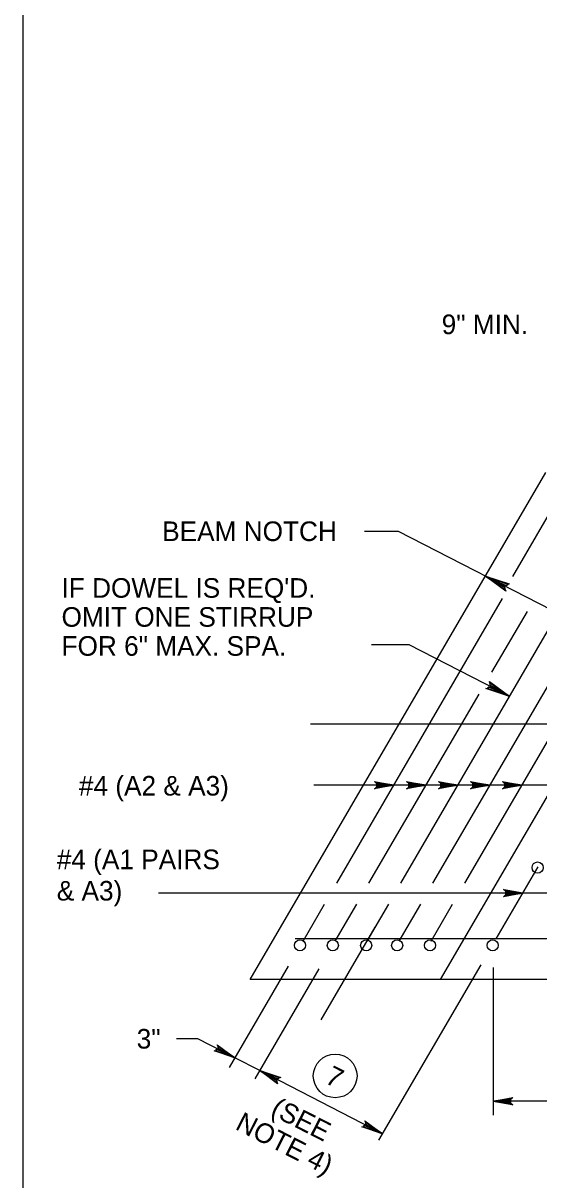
# Model space of a CAD drawing. Extents: x 639331 to 643089, y 299088 to 300975.
# Drawn here: x 641433.1 to 641512, y 299335.4 to 299512.5 of the extents above; entities that cross this region are included whole.
import ezdxf

# ---------------------------------------------------------------- set-up
doc = ezdxf.new("R2010")
doc.units = 0
doc.layers.add('1', color=7, linetype='Continuous')

msp = doc.modelspace()

# ---------------------------------------------------------------- linework, layer by layer
at = {"layer": '1'}
for p, q in [((641433.06, 299102.66), (641433.06, 299666.66)), ((641467.83, 299366.05), (641513.08, 299443.67)), ((641496.98, 299366.05), (641542.23, 299443.67)), ((641508.03, 299427.74), (641513.67, 299437.42)), ((641490.54, 299434.65), (641485.33, 299434.65)), ((641526.26, 299416.28), (641490.54, 299434.65)), ((641481.09, 299380.81), (641506.49, 299424.37)), ((641504.85, 299413.11), (641510.28, 299422.42)), ((641490.91, 299380.81), (641514.04, 299420.49)), ((641492.19, 299417.29), (641486.4, 299417.29)), ((641507.57, 299409.38), (641492.19, 299417.29)), ((641495.81, 299380.81), (641517.81, 299418.55)), ((641500.7, 299380.81), (641521.57, 299416.62)), ((641486.02, 299380.81), (641502.9, 299409.76)), ((641638.33, 299405.17), (641477.08, 299405.17)), ((641489.83, 299395.8), (641477.58, 299395.8)), ((641494.76, 299395.8), (641489.83, 299395.8)), ((641499.65, 299395.8), (641494.76, 299395.8)), ((641504.55, 299395.8), (641499.65, 299395.8)), ((641509.43, 299395.8), (641504.55, 299395.8)), ((641526.15, 299395.8), (641509.43, 299395.8)), ((641505.51, 299372.3), (641511.93, 299383.3)), ((641509.59, 299379.3), (641453.81, 299379.3)), ((641526.97, 299379.3), (641509.59, 299379.3)), ((641475.92, 299371.93), (641479.22, 299377.6)), ((641480.85, 299371.93), (641484.15, 299377.6)), ((641485.74, 299371.93), (641489.04, 299377.6)), ((641490.64, 299371.93), (641493.94, 299377.6)), ((641495.52, 299371.93), (641498.83, 299377.6)), ((641478.72, 299359.9), (641486.98, 299374.06)), ((641618.2, 299372.3), (641474.7, 299372.3)), ((641464.64, 299352.58), (641473.7, 299368.13)), ((641468.57, 299350.87), (641478.39, 299367.72)), ((641487.54, 299341.46), (641503.19, 299368.31)), ((641618.2, 299366.05), (641467.83, 299366.05)), ((641459.81, 299357), (641456.52, 299357)), ((641465.5, 299354.07), (641459.81, 299357)), ((641469.3, 299352.12), (641465.5, 299354.07)), ((641488.11, 299342.45), (641469.3, 299352.12)), ((641594.33, 299347.42), (641505.05, 299347.42))]:
    msp.add_line(p, q, dxfattribs=at)
for points in [[(641506.86, 299425.75), (641506.86, 299426.04), (641503.84, 299427.82), (641506.86, 299425.75), (641506.95, 299425.52), (641503.84, 299427.82), (641507.02, 299426.37), (641507.26, 299426.54), (641503.84, 299427.82), (641507.51, 299426.61), (641507.26, 299426.54)], [(641504.55, 299411.45), (641504.55, 299411.15), (641507.57, 299409.38), (641504.55, 299411.45), (641504.45, 299411.68), (641507.57, 299409.38), (641504.38, 299410.83), (641504.15, 299410.65), (641507.57, 299409.38), (641503.89, 299410.59), (641504.15, 299410.65)], [(641489.83, 299395.8), (641486.85, 299395.24), (641486.96, 299395.32), (641487.08, 299395.4), (641487.14, 299395.5), (641487.2, 299395.6), (641487.21, 299395.7), (641487.23, 299395.8), (641487.21, 299395.9), (641487.2, 299396), (641487.14, 299396.1), (641487.08, 299396.2), (641486.96, 299396.28), (641486.85, 299396.36), (641489.83, 299395.8), (641486.96, 299396.28), (641487.08, 299396.2), (641489.83, 299395.8), (641487.14, 299396.1), (641487.2, 299396), (641489.83, 299395.8), (641487.21, 299395.9), (641487.23, 299395.8), (641489.83, 299395.8), (641487.21, 299395.7), (641487.2, 299395.6), (641489.83, 299395.8), (641487.14, 299395.5), (641487.08, 299395.4), (641489.83, 299395.8), (641486.96, 299395.32)], [(641494.76, 299395.8), (641491.77, 299395.24), (641491.89, 299395.32), (641492, 299395.4), (641492.06, 299395.5), (641492.12, 299395.6), (641492.14, 299395.7), (641492.16, 299395.8), (641492.14, 299395.9), (641492.12, 299396), (641492.06, 299396.1), (641492, 299396.2), (641491.89, 299396.28), (641491.77, 299396.36), (641494.76, 299395.8), (641491.89, 299396.28), (641492, 299396.2), (641494.76, 299395.8), (641492.06, 299396.1), (641492.12, 299396), (641494.76, 299395.8), (641492.14, 299395.9), (641492.16, 299395.8), (641494.76, 299395.8), (641492.14, 299395.7), (641492.12, 299395.6), (641494.76, 299395.8), (641492.06, 299395.5), (641492, 299395.4), (641494.76, 299395.8), (641491.89, 299395.32)], [(641499.65, 299395.8), (641496.67, 299395.24), (641496.78, 299395.32), (641496.89, 299395.4), (641496.95, 299395.5), (641497.01, 299395.6), (641497.03, 299395.7), (641497.05, 299395.8), (641497.03, 299395.9), (641497.01, 299396), (641496.95, 299396.1), (641496.89, 299396.2), (641496.78, 299396.28), (641496.67, 299396.36), (641499.65, 299395.8), (641496.78, 299396.28), (641496.89, 299396.2), (641499.65, 299395.8), (641496.95, 299396.1), (641497.01, 299396), (641499.65, 299395.8), (641497.03, 299395.9), (641497.05, 299395.8), (641499.65, 299395.8), (641497.03, 299395.7), (641497.01, 299395.6), (641499.65, 299395.8), (641496.95, 299395.5), (641496.89, 299395.4), (641499.65, 299395.8), (641496.78, 299395.32)], [(641504.55, 299395.8), (641501.56, 299395.24), (641501.68, 299395.32), (641501.79, 299395.4), (641501.85, 299395.5), (641501.91, 299395.6), (641501.93, 299395.7), (641501.95, 299395.8), (641501.93, 299395.9), (641501.91, 299396), (641501.85, 299396.1), (641501.79, 299396.2), (641501.68, 299396.28), (641501.56, 299396.36), (641504.55, 299395.8), (641501.68, 299396.28), (641501.79, 299396.2), (641504.55, 299395.8), (641501.85, 299396.1), (641501.91, 299396), (641504.55, 299395.8), (641501.93, 299395.9), (641501.95, 299395.8), (641504.55, 299395.8), (641501.93, 299395.7), (641501.91, 299395.6), (641504.55, 299395.8), (641501.85, 299395.5), (641501.79, 299395.4), (641504.55, 299395.8), (641501.68, 299395.32)], [(641509.43, 299395.8), (641506.45, 299395.24), (641506.57, 299395.32), (641506.68, 299395.4), (641506.74, 299395.5), (641506.8, 299395.6), (641506.82, 299395.7), (641506.83, 299395.8), (641506.82, 299395.9), (641506.8, 299396), (641506.74, 299396.1), (641506.68, 299396.2), (641506.57, 299396.28), (641506.45, 299396.36), (641509.43, 299395.8), (641506.57, 299396.28), (641506.68, 299396.2), (641509.43, 299395.8), (641506.74, 299396.1), (641506.8, 299396), (641509.43, 299395.8), (641506.82, 299395.9), (641506.83, 299395.8), (641509.43, 299395.8), (641506.82, 299395.7), (641506.8, 299395.6), (641509.43, 299395.8), (641506.74, 299395.5), (641506.68, 299395.4), (641509.43, 299395.8), (641506.57, 299395.32)], [(641509.59, 299379.3), (641506.61, 299378.74), (641506.73, 299378.82), (641506.84, 299378.9), (641506.9, 299379), (641506.96, 299379.1), (641506.98, 299379.2), (641506.99, 299379.3), (641506.98, 299379.4), (641506.96, 299379.5), (641506.9, 299379.6), (641506.84, 299379.7), (641506.73, 299379.78), (641506.61, 299379.86), (641509.59, 299379.3), (641506.73, 299379.78), (641506.84, 299379.7), (641509.59, 299379.3), (641506.9, 299379.6), (641506.96, 299379.5), (641509.59, 299379.3), (641506.98, 299379.4), (641506.99, 299379.3), (641509.59, 299379.3), (641506.98, 299379.2), (641506.96, 299379.1), (641509.59, 299379.3), (641506.9, 299379), (641506.84, 299378.9), (641509.59, 299379.3), (641506.73, 299378.82)], [(641505.05, 299367.92), (641505.05, 299345.3)], [(641462.86, 299355.88), (641462.86, 299355.62), (641465.5, 299354.07), (641462.86, 299355.88), (641462.78, 299356.08), (641465.5, 299354.07), (641462.72, 299355.33), (641462.51, 299355.18), (641465.5, 299354.07), (641462.29, 299355.12), (641462.51, 299355.18)], [(641471.94, 299350.31), (641471.94, 299350.57), (641469.3, 299352.12), (641471.94, 299350.31), (641472.02, 299350.11), (641469.3, 299352.12), (641472.08, 299350.86), (641472.29, 299351.01), (641469.3, 299352.12), (641472.51, 299351.06), (641472.29, 299351.01)], [(641505.05, 299347.42), (641508.03, 299347.98), (641507.92, 299347.9), (641507.8, 299347.82), (641507.74, 299347.72), (641507.68, 299347.62), (641507.67, 299347.52), (641507.65, 299347.42), (641507.67, 299347.32), (641507.68, 299347.22), (641507.74, 299347.12), (641507.8, 299347.02), (641507.92, 299346.94), (641508.03, 299346.86), (641505.05, 299347.42), (641507.92, 299346.94), (641507.8, 299347.02), (641505.05, 299347.42), (641507.74, 299347.12), (641507.68, 299347.22), (641505.05, 299347.42), (641507.67, 299347.32), (641507.65, 299347.42), (641505.05, 299347.42), (641507.67, 299347.52), (641507.68, 299347.62), (641505.05, 299347.42), (641507.74, 299347.72), (641507.8, 299347.82), (641505.05, 299347.42), (641507.92, 299347.9)], [(641485.47, 299344.25), (641485.47, 299343.99), (641488.11, 299342.45), (641485.47, 299344.25), (641485.39, 299344.45), (641488.11, 299342.45), (641485.32, 299343.71), (641485.12, 299343.56), (641488.11, 299342.45), (641484.9, 299343.5), (641485.12, 299343.56)]]:
    msp.add_lwpolyline(points, dxfattribs=at)
for centre, radius in [((641511.84, 299383.2), 0.853), ((641475.45, 299371.29), 0.853), ((641480.48, 299371.29), 0.853), ((641485.59, 299371.29), 0.853), ((641490.33, 299371.29), 0.853), ((641495.37, 299371.29), 0.853), ((641504.96, 299371.29), 0.853), ((641480.84, 299351.31), 3.35)]:
    msp.add_circle(centre, radius, dxfattribs=at)

# ---------------------------------------------------------------- texts
for s, rotation, p in [('9" MIN.', 360, (641497.15, 299464.85)), ('BEAM NOTCH', 360, (641454.35, 299433.18)), ('3"', 360, (641450.45, 299355.49)), ('7', 333.0464, (641479.12, 299350.32)), ('(SEE', 333.0464, (641470.79, 299345.44)), ('NOTE 4)', 333.0464, (641465.38, 299343.22))]:
    msp.add_text(s, height=3, rotation=rotation, dxfattribs=at).set_placement(p)
for s, p in [("IF DOWEL IS REQ'D.", (641438.94, 299424.5)), ('OMIT ONE STIRRUP', (641438.94, 299420.06)), ('FOR 6" MAX. SPA.', (641438.94, 299415.62)), ('#4 (A2 & A3)', (641441.6, 299394.22)), ('#4 (A1 PAIRS', (641438.21, 299382.95)), ('& A3)', (641438.21, 299378.15))]:
    msp.add_text(s, height=3, dxfattribs=at).set_placement(p)

doc.saveas('drawing.dxf')
